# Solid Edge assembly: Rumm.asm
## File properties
Title: KNOTTI rrumm 20-242571
Author: Kadik
Comments: F200W 112x5 M12x1,5 re.
Template: KNOTT AKK.asm
Last saved by: Kadik
Revision: 76
Application: Solid Edge
Category: 6A2256.001
ST_ArtikelNr: 6A2265.001
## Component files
plaat rummule.par
Mutter M12.par
rummu pealne asm.asm
Rumm 5 avaga.par
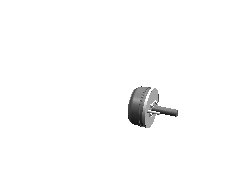
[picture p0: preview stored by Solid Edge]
